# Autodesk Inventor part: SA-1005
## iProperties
Created: 2004-11
Part Number: SA-1005
Cost Center: 0 lbmass
Document SubType Name: Modeling
Designer: busseym
Manufacturer: Standard
Standards Organization: Custom
Stock Number: P-1267
Density: 1 g/cm^3
CAGE: 1LJX3
Dept. ID: Product Design
Description #2: ---
Finish #1: ---
Finish #2: ---
Material ID: ---
Project Number: ---
Author: busseym
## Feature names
1. Extrusion1
2. Extrusion2
3. Extrusion4
4. Circular Pattern1
5. Mirror1
6. Extrusion3
7. Mirror2
